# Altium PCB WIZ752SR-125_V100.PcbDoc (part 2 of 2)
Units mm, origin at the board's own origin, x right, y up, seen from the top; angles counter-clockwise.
Board outline 60 x 85 mm, 4 copper layers (Top Layer, Internal Plane 1, Internal Plane 2, Bottom Layer); 105 components, 107 nets, 391 pads, 152 vias.
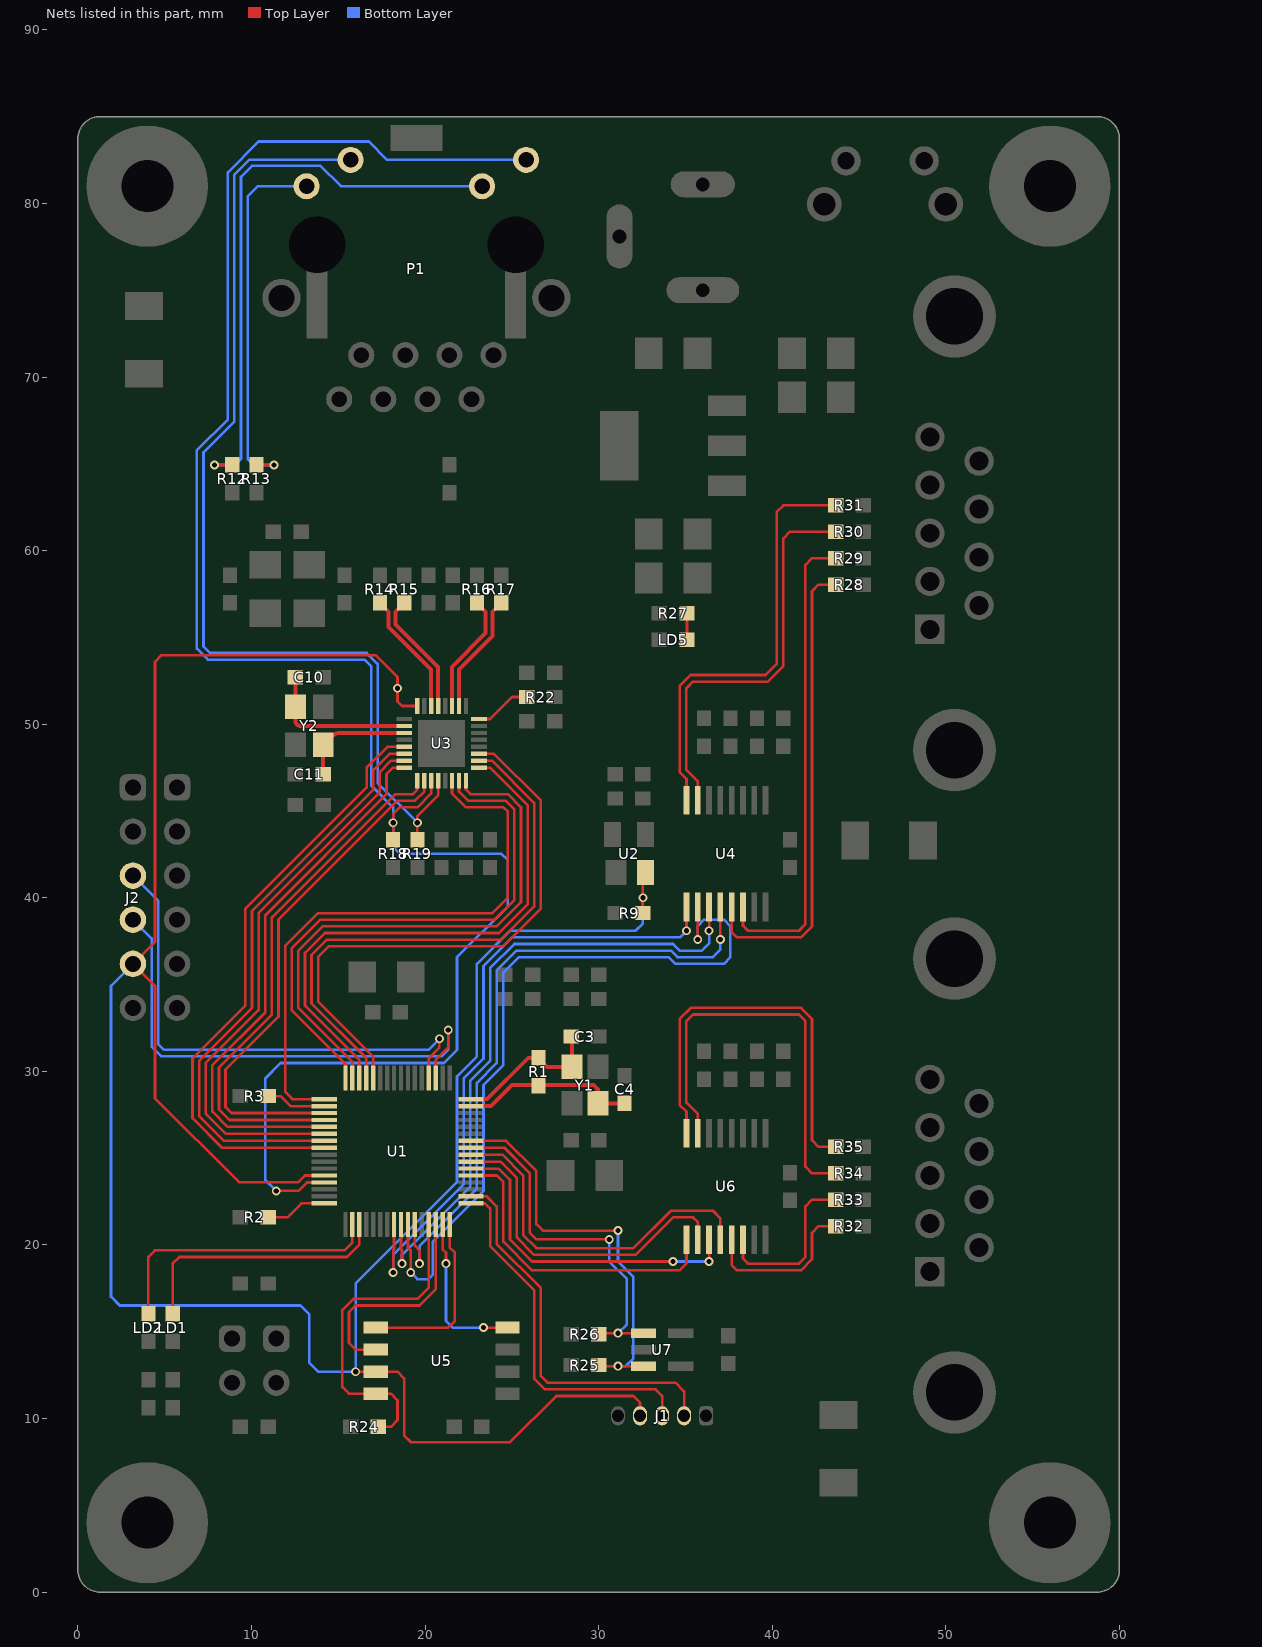
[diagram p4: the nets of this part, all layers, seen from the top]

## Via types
v1: diameter 0.762, hole 0.508, Top Layer to Bottom Layer, tented both sides, 87 vias
v2: diameter 0.508, hole 0.305, Top Layer to Bottom Layer, tented both sides, 65 vias

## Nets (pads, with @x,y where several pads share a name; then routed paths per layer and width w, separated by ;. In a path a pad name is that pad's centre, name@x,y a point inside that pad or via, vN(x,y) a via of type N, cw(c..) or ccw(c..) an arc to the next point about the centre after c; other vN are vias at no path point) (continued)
NetLD5_1: LD5.1 R27.1 | length 1.5
  Top Layer w0.152: LD5.1@35.09,54.864 R27.1@35.09,56.388
NetP1_L1: P1.L1 R13.2 | length 21.4
  Top Layer w0.152: R13.2@10.287,64.935 v2(11.303,64.935)
  Bottom Layer w0.152: v2(11.303,64.935) 10.122,64.935 9.779,65.278 9.779,80.391 10.378,80.99 P1.L1@13.175,80.99
NetP1_L3: P1.L3 R12.2 | length 33.6
  Top Layer w0.152: v2(7.874,64.935) R12.2@8.89,64.935
  Bottom Layer w0.152: v2(7.874,64.935) 9.055,64.935 9.398,65.278 9.398,81.534 10.033,82.169 13.97,82.169 15.149,80.99 P1.L3@23.285,80.99
NetR2_2: R2.2 U1.32 | length 3.6
  Top Layer w0.152: R2.2@10.96,21.59 12.065,21.59 12.875,22.4 U1.32@14.19,22.4
NetR3_2: R3.2 U1.18 | length 3.5
  Top Layer w0.152: R3.2@10.96,28.575 11.684,28.575 12.259,28 U1.18@14.19,28
NetR14_2: R14.2 U3.30 | length 7.2
  Top Layer w0.229: R14.2@17.399,56.985 17.907,56.477 17.907,55.595 20.355,53.147 U3.30@20.355,51.045
NetR15_2: R15.2 U3.29 | length 7.2
  Top Layer w0.229: R15.2@18.796,56.985 18.288,56.477 18.288,55.753 20.755,53.286 U3.29@20.755,51.045
NetR16_2: R16.2 U3.27 | length 7
  Top Layer w0.229: U3.27@21.555,51.045 21.555,53.305 23.495,55.245 23.495,56.477 R16.2@22.987,56.985
NetR17_2: R17.2 U3.26 | length 6.9
  Top Layer w0.229: U3.26@21.955,51.045 21.955,53.147 23.876,55.068 23.876,56.477 R17.2@24.384,56.985
NetR24_1: R24.1 U1.45 U5.4 | length 19.5
  Top Layer w0.152: R24.1@17.31,9.525 18.034,9.525 18.415,9.906 18.415,11.049 18.034,11.43 U5.4@17.155,11.43 15.621,11.43 15.24,11.811 15.24,16.256 15.875,16.891 19.558,16.891 20.215,17.548 U1.45@20.215,21.175
NetR25_1: R25.1 U1.58 U7.3 | length 23.8
  Top Layer w0.152: U1.58@22.64,26 24.673,26 26.416,24.257 26.416,21.209 26.797,20.828 v2(31.115,20.828) ; R25.1@30.01,13.081 30.071,13.02 v2(31.115,13.02) U7.3@32.58,13.02
  Bottom Layer w0.152: v2(31.115,13.02) 31.562,13.02 32.004,13.462 32.004,18.161 31.115,19.05 v2(31.115,20.828)
NetR26_1: R26.1 U1.57 U7.1 | length 20.8
  Top Layer w0.152: U1.57@22.64,25.6 24.565,25.6 26.035,24.13 26.035,20.701 26.416,20.32 v2(30.607,20.32) ; R26.1@30.01,14.859 30.071,14.92 v2(31.115,14.92) U7.1@32.58,14.92
  Bottom Layer w0.152: v2(30.607,20.32) 30.607,19.05 31.623,18.034 31.623,15.428 v2(31.115,14.92)
NetR28_1: R28.1 U4.13 | length 27.3
  Top Layer w0.152: U4.13@37.663,39.471 37.663,38.029 37.973,37.719 41.656,37.719 42.291,38.354 42.291,57.658 42.672,58.039 R28.1@43.65,58.039
NetR29_1: R29.1 U4.14 | length 27.6
  Top Layer w0.152: U4.14@38.313,39.471 38.313,38.395 38.608,38.1 41.529,38.1 41.91,38.481 41.91,59.182 42.291,59.563 R29.1@43.65,59.563
NetR30_1: R30.1 U4.7 | length 23.4
  Top Layer w0.152: U4.7@35.713,45.619 35.713,46.71 35.052,47.371 35.052,52.07 35.433,52.451 39.751,52.451 40.64,53.34 40.64,60.706 41.021,61.087 R30.1@43.65,61.087
NetR31_1: R31.1 U4.8 | length 25.2
  Top Layer w0.152: U4.8@35.063,45.619 35.063,46.852 34.671,47.244 34.671,52.197 35.306,52.832 39.624,52.832 40.259,53.467 40.259,62.23 40.64,62.611 R31.1@43.65,62.611
NetR32_1: R32.1 U6.13 | length 9.5
  Top Layer w0.152: U6.13@37.663,20.294 37.663,18.852 37.973,18.542 41.656,18.542 42.291,19.177 42.291,20.701 42.672,21.082 R32.1@43.65,21.082
NetR33_1: R33.1 U6.14 | length 9.8
  Top Layer w0.152: U6.14@38.313,20.294 38.313,19.218 38.608,18.923 41.529,18.923 41.91,19.304 41.91,22.225 42.291,22.606 R33.1@43.65,22.606
NetR34_1: R34.1 U6.7 | length 24.2
  Top Layer w0.152: U6.7@35.713,26.443 35.713,27.533 35.052,28.194 35.052,32.893 35.433,33.274 41.529,33.274 41.91,32.893 41.91,24.511 42.291,24.13 R34.1@43.65,24.13
NetR35_1: R35.1 U6.8 | length 23.4
  Top Layer w0.152: U6.8@35.063,26.443 35.063,27.675 34.671,28.067 34.671,33.02 35.306,33.655 41.656,33.655 42.291,33.02 42.291,26.035 42.672,25.654 R35.1@43.65,25.654
NetU1_40: U1.40 U4.9 | length 36.5
  Top Layer w0.152: v2(18.161,18.415) 18.161,19.685 18.215,19.739 U1.40@18.215,21.175 ; v2(35.063,38.1) U4.9@35.063,39.471
  Bottom Layer w0.152: v2(18.161,18.415) 18.161,19.431 22.225,23.495 22.225,29.591 23.368,30.734 23.368,36.068 25.019,37.719 34.682,37.719 v2(35.063,38.1)
NetU1_41: U1.41 U4.11 | length 37
  Top Layer w0.152: U1.41@18.615,21.175 18.615,19.739 18.669,19.685 v2(18.669,18.923) ; v2(36.363,38.1) U4.11@36.363,39.471
  Bottom Layer w0.152: v2(18.669,18.923) 18.669,19.431 22.606,23.368 22.606,29.464 23.749,30.607 23.749,35.941 25.146,37.338 34.29,37.338 34.671,36.957 35.941,36.957 36.363,37.379 v2(36.363,38.1)
NetU1_42: U1.42 U4.10 | length 43.8
  Top Layer w0.152: U1.42@19.015,21.175 19.015,19.847 19.177,19.685 v2(19.177,18.415) ; v2(35.713,37.592) U4.10@35.713,39.471
  Bottom Layer w0.152: v2(19.177,18.415) 19.558,18.034 20.193,18.034 20.447,18.288 20.447,20.193 23.368,23.114 23.368,29.21 24.511,30.353 24.511,35.687 25.4,36.576 34.036,36.576 34.417,36.195 37.211,36.195 37.592,36.576 37.592,38.354 37.211,38.735 36.068,38.735 35.713,38.38 v2(35.713,37.592)
NetU1_43: U1.43 U4.12 | length 37.2
  Top Layer w0.152: U1.43@19.415,21.175 19.415,19.955 19.685,19.685 v2(19.685,18.923) ; v2(37.013,37.592) U4.12@37.013,39.471
  Bottom Layer w0.152: v2(19.685,18.923) 19.685,19.939 22.987,23.241 22.987,29.337 24.13,30.48 24.13,35.814 25.273,36.957 34.163,36.957 34.544,36.576 36.576,36.576 37.013,37.013 v2(37.013,37.592)
NetU1_46: U1.46 U5.2 | length 12.7
  Top Layer w0.152: U5.2@17.155,13.97 16.002,13.97 15.621,14.351 15.621,16.129 16.002,16.51 19.685,16.51 20.615,17.44 U1.46@20.615,21.175
NetU1_47: U1.47 U5.8 | length 9.3
  Top Layer w0.152: U1.47@21.015,21.175 21.015,19.752 21.209,19.558 v2(21.209,18.923) ; v2(23.368,15.24) U5.8@24.755,15.24
  Bottom Layer w0.152: v2(21.209,18.923) 21.209,15.621 21.59,15.24 v2(23.368,15.24)
NetU1_48: U1.48 U5.1 | length 10.4
  Top Layer w0.152: U5.1@17.155,15.24 21.336,15.24 21.717,15.621 21.717,19.558 21.415,19.86 U1.48@21.415,21.175
NetU1_53: U1.53 U6.9 | length 18.2
  Top Layer w0.152: U1.53@22.64,24 24.133,24 24.511,23.622 24.511,20.193 26.162,18.542 34.671,18.542 35.063,18.934 U6.9@35.063,20.294
NetU1_54: U1.54 U6.11 | length 19.2
  Top Layer w0.152: U1.54@22.64,24.4 24.241,24.4 24.892,23.749 24.892,20.32 26.162,19.05 v2(34.29,19.05) ; v2(36.363,19.05) U6.11@36.363,20.294
  Bottom Layer w0.152: v2(34.29,19.05) v2(36.363,19.05)
NetU1_55: U1.55 U6.10 | length 19.3
  Top Layer w0.152: U1.55@22.64,24.8 24.349,24.8 25.273,23.876 25.273,20.447 26.289,19.431 32.131,19.431 34.29,21.59 35.433,21.59 35.713,21.31 U6.10@35.713,20.294
NetU1_56: U1.56 U6.12 | length 20.9
  Top Layer w0.152: U1.56@22.64,25.2 24.457,25.2 25.654,24.003 25.654,20.574 26.416,19.812 32.004,19.812 34.163,21.971 36.576,21.971 37.013,21.534 U6.12@37.013,20.294
PHY_AD0: P1.L4 R18.1 U1.29 U3.11 | length 113.3
  Top Layer w0.152: v2(11.43,23.114) 12.7,23.114 13.186,23.6 U1.29@14.19,23.6 ; R18.1@18.161,43.345 v2(18.161,44.323) 18.161,44.831 18.542,45.212 19.558,45.212 20.355,46.009 U3.11@20.355,46.745
  Bottom Layer w0.152: v2(11.43,23.114) 10.795,23.749 10.795,29.591 11.684,30.48 21.082,30.48 21.844,31.242 21.844,36.576 24.765,39.497 24.765,42.164 24.384,42.545 18.542,42.545 18.161,42.926 v2(18.161,44.323) 18.161,45.212 16.891,46.482 16.891,53.34 16.51,53.721 7.493,53.721 6.858,54.356 6.858,65.786 8.636,67.564 8.636,81.788 10.414,83.566 16.764,83.566 17.82,82.51 P1.L4@25.825,82.51
PHY_AD3: P1.L2 R19.1 U3.12 | length 59.4
  Top Layer w0.152: R19.1@19.558,43.345 v2(19.558,44.323) 19.558,44.704 20.755,45.901 U3.12@20.755,46.745
  Bottom Layer w0.152: P1.L2@15.715,82.51 9.866,82.51 9.017,81.661 9.017,67.437 7.239,65.659 7.239,54.483 7.62,54.102 16.637,54.102 17.272,53.467 17.272,46.609 v2(19.558,44.323)
RSTN: J1.4 J2.5 R9.1 U1.28 U2.2 U3.32 U5.3 | length 155.4
  Top Layer w0.152: U1.28@14.19,24 13.078,24 12.7,23.622 9.271,23.622 4.445,28.448 4.445,34.925 J2.5@3.175,36.195 4.445,37.465 4.445,53.594 4.826,53.975 17.145,53.975 18.415,52.705 v2(18.415,52.07) 18.415,51.308 18.678,51.045 U3.32@19.555,51.045 ; v2(16.002,12.7) U5.3@17.155,12.7 18.415,12.7 18.796,12.319 18.796,9.017 19.177,8.636 24.892,8.636 27.559,11.303 32.004,11.303 32.385,10.922 J1.4@32.385,10.16 ; R9.1@32.55,39.116 v2(32.55,40.005) 32.55,41.295 U2.2@32.7,41.445
  Bottom Layer w0.152: J2.5@3.175,36.195 1.905,34.925 1.905,17.018 2.413,16.51 12.827,16.51 13.335,16.002 13.335,13.208 13.843,12.7 v2(16.002,12.7) 16.002,17.78 21.844,23.622 21.844,29.718 22.987,30.861 22.987,36.195 24.892,38.1 32.131,38.1 32.55,38.519 v2(32.55,40.005)
RXC: U1.17 U3.14 | length 34.1
  Top Layer w0.152: U1.17@14.19,28.4 12.367,28.4 11.938,28.829 11.938,37.211 13.843,39.116 23.876,39.116 24.765,40.005 24.765,44.958 24.511,45.212 22.352,45.212 21.555,46.009 U3.14@21.555,46.745
RXD0: U1.13 U3.18 | length 32.5
  Top Layer w0.152: U1.13@16.615,29.625 16.615,30.756 13.462,33.909 13.462,36.703 14.351,37.592 24.384,37.592 26.289,39.497 26.289,45.466 23.86,47.895 U3.18@23.105,47.895
RXD1: U1.14 U3.17 | length 31.9
  Top Layer w0.152: U1.14@16.215,29.625 16.215,30.648 13.081,33.782 13.081,36.83 14.224,37.973 24.257,37.973 25.908,39.624 25.908,45.339 23.752,47.495 U3.17@23.105,47.495
RXD2: U1.15 U3.16 | length 32.2
  Top Layer w0.152: U1.15@15.815,29.625 15.815,30.54 12.7,33.655 12.7,36.957 14.097,38.354 24.13,38.354 25.527,39.751 25.527,45.212 24.765,45.974 22.606,45.974 22.355,46.225 U3.16@22.355,46.745
RXD3: U1.16 U3.15 | length 32.2
  Top Layer w0.152: U1.16@15.415,29.625 15.415,30.432 12.319,33.528 12.319,37.084 13.97,38.735 24.003,38.735 25.146,39.878 25.146,45.085 24.638,45.593 22.479,45.593 21.955,46.117 U3.15@21.955,46.745
RXDV: U1.12 U3.19 | length 33.2
  Top Layer w0.152: U1.12@17.015,29.625 17.015,30.864 13.843,34.036 13.843,36.576 14.478,37.211 24.511,37.211 26.67,39.37 26.67,45.593 23.968,48.295 U3.19@23.105,48.295
STATUS_1: LD1.2 U1.35 | length 15.2
  Top Layer w0.152: LD1.2@5.461,16.04 5.461,18.923 5.842,19.304 15.494,19.304 16.215,20.025 U1.35@16.215,21.175
STATUS_2: LD2.2 U1.34 | length 16.4
  Top Layer w0.152: LD2.2@4.064,16.04 4.064,19.304 4.445,19.685 15.367,19.685 15.815,20.133 U1.34@15.815,21.175
SWCLK: J1.3 U1.49 | length 21
  Top Layer w0.152: U1.49@22.64,22.4 23.447,22.4 23.749,22.098 23.749,19.939 26.289,17.399 26.289,12.319 26.924,11.684 33.274,11.684 33.655,11.303 J1.3@33.655,10.16
SWDIO: J1.2 U1.50 | length 22.6
  Top Layer w0.152: U1.50@22.64,22.8 23.555,22.8 24.13,22.225 24.13,20.066 26.67,17.526 26.67,12.446 27.051,12.065 34.417,12.065 34.925,11.557 J1.2@34.925,10.16
TEST: R22.1 U3.24 | length 3.3
  Top Layer w0.152: U3.24@23.105,50.295 23.752,50.295 25.019,51.562 R22.1@25.87,51.562
TXC: U1.19 U3.10 | length 30
  Top Layer w0.152: U1.19@14.19,27.6 8.849,27.6 8.509,27.94 8.509,30.099 11.557,33.147 11.557,38.735 18.415,45.593 19.431,45.593 19.955,46.117 U3.10@19.955,46.745
TXD00: U1.20 U3.9 | length 30.6
  Top Layer w0.152: U1.20@14.19,27.2 8.741,27.2 8.128,27.813 8.128,30.226 11.176,33.274 11.176,38.862 18.288,45.974 19.304,45.974 19.555,46.225 U3.9@19.555,46.745
TXD1: U1.21 U3.8 | length 31.6
  Top Layer w0.152: U1.21@14.19,26.8 8.633,26.8 7.747,27.686 7.747,30.353 10.795,33.401 10.795,38.989 17.78,45.974 17.78,47.117 18.158,47.495 U3.8@18.805,47.495
TXD2: U1.22 U3.7 | length 32.8
  Top Layer w0.152: U1.22@14.19,26.4 8.525,26.4 7.366,27.559 7.366,30.48 10.414,33.528 10.414,39.116 17.399,46.101 17.399,47.244 18.05,47.895 U3.7@18.805,47.895
TXD3: U1.23 U3.6 | length 34.1
  Top Layer w0.152: U1.23@14.19,26 8.417,26 6.985,27.432 6.985,30.607 10.033,33.655 10.033,39.243 17.018,46.228 17.018,47.371 17.942,48.295 U3.6@18.805,48.295
TXEN: U1.24 U3.5 | length 35.3
  Top Layer w0.152: U1.24@14.19,25.6 8.309,25.6 6.604,27.305 6.604,30.734 9.652,33.782 9.652,39.37 16.637,46.355 16.637,47.498 17.834,48.695 U3.5@18.805,48.695
U_RXD2: J2.3 U1.4 | length 29.4
  Top Layer w0.152: U1.4@20.215,29.625 20.215,30.756 20.828,31.369 v2(20.828,31.877)
  Bottom Layer w0.152: J2.3@3.175,41.275 4.635,39.814 4.635,31.559 4.953,31.242 20.193,31.242 v2(20.828,31.877)
U_TXD2: J2.4 U1.3 | length 29.4
  Top Layer w0.152: U1.3@20.615,29.625 20.615,30.648 21.336,31.369 v2(21.336,32.385)
  Bottom Layer w0.152: J2.4@3.175,38.735 4.255,37.655 4.255,31.432 4.826,30.861 20.955,30.861 21.336,31.242 v2(21.336,32.385)
XIN: C4.2 R1.1 U1.63 Y1.3 | length 10.3
  Top Layer w0.229: U1.63@22.64,28 23.809,28 25.019,29.21 29.718,29.21 29.96,28.968 Y1.3@29.96,28.16 31.492,28.16 C4.2@31.496,28.156
XOUT: C3.2 R1.2 U1.64 Y1.1 | length 8.8
  Top Layer w0.229: U1.64@22.64,28.4 23.574,28.4 25.946,30.772 R1.2@26.543,30.772 26.543,30.734 27.017,30.26 Y1.1@28.46,30.26 28.46,31.954 C3.2@28.41,32.004
XTAL1: C10.2 U3.2 Y2.1 | length 8.9
  Top Layer w0.229: C10.2@12.535,52.705 Y2.1@12.535,51.011 12.535,50.203 ccw(c12.843,50.203) 12.843,49.895 U3.2@18.805,49.895
XTAL2: C11.2 U3.3 Y2.3 | length 6.6
  Top Layer w0.229: C11.2@14.135,47.117 Y2.3@14.135,48.811 14.605,49.281 cw(c15.122,48.764) 15.122,49.495 U3.3@18.805,49.495
pads on no net: J6.1 J6.4 J6.6 J6.9 J7.1 J7.4 J7.6 J7.9 P1. P1.R4 P1.R5 P1.R6 U1.30 U1.31 U1.33 U1.37 U1.38 U1.44 U1.51 U1.52 U1.59 U1.60 U3.1 U3.21

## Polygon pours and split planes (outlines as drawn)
CH_GND on Top Layer "Top Layer-net" (solid, remove dead copper, pour order 18): 0.762,7.366 0.508,7.112 0.508,1.016 1.016,0.508 1.651,0.508 59.055,0.508 59.563,1.016 59.563,1.778 59.563,83.947 59.055,84.455 58.801,84.455 51.943,84.455 51.689,84.201 51.689,83.947 51.689,81.534 51.308,81.153 50.927,81.153 42.037,81.153 41.783,80.899 41.783,80.518 41.783,78.613 42.037,78.359 42.926,78.359 47.117,78.359 47.498,77.978 47.498,77.597 47.498,69.723 47.752,69.469 48.514,69.469 54.356,69.469 54.737,69.088 54.737,68.58 54.737,52.832 54.356,52.451 53.975,52.451 47.879,52.451 47.498,52.07 47.498,49.403 47.498,32.893 47.879,32.512 54.356,32.512 54.737,32.131 54.737,31.496 54.737,15.875 54.356,15.494 53.594,15.494 47.879,15.494 47.498,15.113 47.498,14.859 47.498,7.747 47.117,7.366 46.736,7.366
GND on Top Layer "Top Layer-net" (solid, remove dead copper, pour order 14): 29.464,69.977 29.21,70.231 29.21,70.358 29.21,72.771 30.226,73.787 30.226,81.026 31.242,82.042 32.258,82.042 37.719,82.042 37.973,81.788 37.973,81.534 37.973,80.391 37.719,80.137 37.338,80.137 33.401,80.137 33.02,79.756 33.02,79.375 33.02,74.168 33.782,73.406 34.036,73.152 34.036,71.247 34.036,70.231 33.782,69.977
IP_3.3V on Top Layer "Top Layer-net" (solid, remove dead copper, pour order 10): 20.574,44.831 20.447,44.704 20.447,42.926 20.574,42.799 22.86,42.799 22.86,44.704 22.733,44.831
3.3V on Top Layer "Top Layer-net" (solid, remove dead copper, pour order 6): 21.844,42.291 21.844,40.386 21.971,40.259 24.13,40.259 24.257,40.386 24.257,42.164 24.13,42.291
3.3V on Top Layer "Top Layer-net" (solid, remove dead copper, pour order 4): 34.036,56.007 33.782,55.753 33.274,55.753 29.464,55.753 29.21,56.007 29.21,56.642 29.21,69.215 29.464,69.469 29.845,69.469 33.782,69.469 34.036,69.215 34.036,68.834 34.036,67.183 34.417,66.802 34.798,66.802 38.608,66.802 38.735,66.675 38.735,66.421 38.735,65.405 38.608,65.278 38.1,65.278 34.417,65.278 34.036,64.897
5V on Top Layer "Top Layer-net" (solid, remove dead copper, pour order 2): 34.544,69.977 34.544,67.818 34.798,67.564 35.433,67.564 39.751,67.564 42.037,67.564 42.291,67.818 42.291,68.199 42.291,75.819 42.037,76.073 41.783,76.073 33.782,76.073 33.528,75.819 33.528,74.803 33.528,74.422 34.544,73.406
CH_GND on Top Layer "Top Layer-net" (solid, remove dead copper, pour order 0): 0.762,73.152 0.508,73.406 0.508,83.947 1.016,84.455 10.541,84.455 10.795,84.201 10.795,83.82 10.795,77.597 12.573,75.819 12.827,75.565 12.827,74.168 12.827,73.406 12.573,73.152
GND on Top Layer "Top Layer-gnd" (solid, remove dead copper, pour order 28): 0.762,70.993 0.508,70.739 0.508,9.144 0.762,8.89 41.275,8.89 41.783,9.398 45.72,9.398 45.974,9.652 45.974,41.021 45.593,41.402 45.593,45.212 45.974,45.593 45.974,75.819 45.72,76.073 45.466,76.073 42.933,76.073 42.679,75.819 42.679,67.571 42.291,67.183 41.656,67.183 39.37,67.183 39.116,66.929 39.116,65.151 38.862,64.897 38.1,64.897 34.585,64.897 34.424,64.736 34.424,55.633 34.163,55.372 29.21,55.372 28.829,55.753 28.829,65.659 28.575,65.913 6.604,65.913 6.223,66.294 6.223,70.739 5.969,70.993
5V on Bottom Layer "Top Layer-net" (solid, remove dead copper, pour order 22): 33.782,76.073 33.528,75.819 33.528,74.422 34.544,73.406 34.544,71.247 34.544,70.104 34.798,69.85 39.116,69.85 39.37,70.104 39.37,75.819 39.116,76.073
CH_GND on Bottom Layer "Top Layer-net" (solid, remove dead copper, pour order 20): 1.016,84.455 0.508,83.947 0.508,73.406 0.762,73.152 7.493,73.152 7.747,73.406 7.747,84.201 7.493,84.455
CH_GND on Bottom Layer "Top Layer-net" (solid, remove dead copper, pour order 16): 0.762,7.366 0.508,7.112 0.508,1.016 1.016,0.508 1.651,0.508 59.055,0.508 59.563,1.016 59.563,1.778 59.563,83.947 59.055,84.455 58.801,84.455 51.943,84.455 51.689,84.201 51.689,83.947 51.689,81.534 51.308,81.153 50.927,81.153 42.037,81.153 41.783,80.899 41.783,80.518 41.783,78.613 42.037,78.359 42.926,78.359 47.117,78.359 47.498,77.978 47.498,77.597 47.498,69.723 47.752,69.469 48.514,69.469 54.356,69.469 54.737,69.088 54.737,68.58 54.737,52.832 54.356,52.451 53.975,52.451 47.879,52.451 47.498,52.07 47.498,49.403 47.498,32.893 47.879,32.512 54.356,32.512 54.737,32.131 54.737,31.496 54.737,15.875 54.356,15.494 53.594,15.494 47.879,15.494 47.498,15.113 47.498,14.859 47.498,7.747 47.117,7.366 46.736,7.366
IP_3.3V on Bottom Layer "Top Layer-net" (solid, remove dead copper, pour order 12): 20.574,44.831 20.447,44.704 20.447,43.942 20.574,43.815 22.733,43.815 22.86,43.942 22.86,44.704 22.733,44.831
3.3V on Bottom Layer "Top Layer-net" (solid, remove dead copper, pour order 8): 21.971,41.275 21.844,41.148 21.844,40.386 21.971,40.259 24.13,40.259 24.257,40.386 24.257,41.148 24.13,41.275
3.3V on Bottom Layer "Top Layer-gnd" (solid, remove dead copper, pour order 24): 29.464,62.23 29.21,61.976 29.21,61.849 29.21,59.944 29.464,59.69 31.496,59.69 31.75,59.944 31.75,61.976 31.496,62.23
GND on Bottom Layer "Top Layer-gnd" (solid, remove dead copper, pour order 30): 0.762,70.993 0.508,70.739 0.508,70.612 0.508,9.144 0.762,8.89 45.72,8.89 45.974,9.144 45.974,10.287 45.974,75.819 45.72,76.073 45.212,76.073 40.005,76.073 34.036,76.073 33.782,75.819 33.782,75.184 33.782,73.914 33.401,73.533 32.893,73.533 29.972,73.533 29.21,72.771 29.083,72.644 29.083,71.628 29.083,66.294 28.702,65.913 28.448,65.913 6.604,65.913 6.223,66.294 6.223,70.739 5.969,70.993
GND on Internal Plane 1 (split plane): 45.972,68.707 45.981,68.587 46.009,68.471 46.055,68.36 46.118,68.258 46.196,68.167 46.287,68.089 46.389,68.026 46.5,67.98 46.616,67.952 46.736,67.943 53.211,67.943 53.211,53.977 46.736,53.977 46.616,53.968 46.5,53.94 46.389,53.894 46.287,53.831 46.196,53.753 46.118,53.662 46.055,53.56 46.009,53.449 45.981,53.333 45.972,53.213 45.972,31.75 45.981,31.63 46.009,31.514 46.055,31.403 46.118,31.301 46.196,31.21 46.287,31.132 46.389,31.069 46.5,31.023 46.616,30.995 46.736,30.986 53.211,30.986 53.211,17.02 46.736,17.02 46.616,17.011 46.5,16.983 46.389,16.937 46.287,16.874 46.196,16.796 46.118,16.705 46.055,16.603 46.009,16.492 45.981,16.376 45.972,16.256 45.972,8.892 0.51,8.892 0.51,71.372 6.221,71.372 6.221,66.675 6.23,66.555 6.258,66.439 6.304,66.328 6.367,66.226 6.445,66.135 6.536,66.057 6.638,65.994 6.749,65.948 6.865,65.92 6.985,65.911 28.321,65.911 28.441,65.92 28.557,65.948 28.668,65.994 28.77,66.057 28.861,66.135 28.939,66.226 29.002,66.328 29.048,66.439 29.076,66.555 29.085,66.675 29.085,72.708 29.908,73.531 33.02,73.531 33.14,73.54 33.256,73.568 33.367,73.614 33.469,73.677 33.56,73.755 33.638,73.846 33.701,73.948 33.747,74.059 33.775,74.175 33.784,74.295 33.784,76.706 45.972,76.706
CH_GND on Internal Plane 1 (split plane): 154 vertices, not listed, extent 0.509,0.509 59.491,84.491
IP_3.3V on Internal Plane 2 (split plane): 6.221,66.675 6.23,66.555 6.258,66.439 6.304,66.328 6.367,66.226 6.445,66.135 6.536,66.057 6.638,65.994 6.749,65.948 6.865,65.92 6.985,65.911 26.414,65.911 26.414,53.975 26.423,53.909 26.448,53.847 26.489,53.794 26.542,53.753 26.604,53.728 26.67,53.719 28.954,53.719 28.954,42.801 20.32,42.801 20.254,42.792 20.192,42.767 20.139,42.726 20.098,42.673 20.073,42.611 20.064,42.545 20.064,39.626 9.146,39.626 9.146,48.895 9.137,48.961 9.112,49.023 9.071,49.076 9.018,49.117 8.956,49.142 8.89,49.151 0.51,49.151 0.51,71.372 6.221,71.372
3.3V on Internal Plane 2 (split plane): 45.972,68.707 45.974,68.677 45.974,53.243 45.972,53.213 45.972,31.75 45.974,31.72 45.974,16.286 45.972,16.256 45.972,8.892 0.51,8.892 0.51,48.639 8.634,48.639 8.634,39.37 8.643,39.304 8.668,39.242 8.709,39.189 8.762,39.148 8.824,39.123 8.89,39.114 20.32,39.114 20.386,39.123 20.448,39.148 20.501,39.189 20.542,39.242 20.567,39.304 20.576,39.37 20.576,42.289 29.21,42.289 29.276,42.298 29.338,42.323 29.391,42.364 29.432,42.417 29.457,42.479 29.466,42.545 29.466,53.975 29.457,54.041 29.432,54.103 29.391,54.156 29.338,54.197 29.276,54.222 29.21,54.231 26.926,54.231 26.926,65.911 28.321,65.911 28.441,65.92 28.557,65.948 28.668,65.994 28.77,66.057 28.861,66.135 28.939,66.226 29.002,66.328 29.048,66.439 29.076,66.555 29.085,66.675 29.085,72.708 29.908,73.531 33.02,73.531 33.14,73.54 33.256,73.568 33.367,73.614 33.469,73.677 33.56,73.755 33.638,73.846 33.701,73.948 33.747,74.059 33.775,74.175 33.784,74.295 33.784,76.706 45.972,76.706

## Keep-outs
Keep-Out Layer:
  the board outline again, w0.127
  text ".Layer_Name" at 9.398,92.71 h1.52

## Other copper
Top Layer:
  pour cut-out: 27.432,28.448 27.686,28.194 27.686,27.432 27.813,27.305 32.004,27.305 32.131,27.432 32.131,30.988 32.004,31.115 31.115,31.115 30.861,31.369 30.861,32.639 30.734,32.766 25.908,32.766 25.781,32.639 25.781,28.575 25.908,28.448
  pour cut-out: 11.938,53.467 11.684,53.213 11.684,46.609 11.938,46.355 14.732,46.355 14.986,46.609 14.986,53.213 14.732,53.467
  text ".Layer_Name" at 9.398,92.71 h1.52
Bottom Layer:
  pour cut-out: 27.813,31.115 27.686,30.988 27.686,27.432 27.813,27.305 30.607,27.305 30.734,27.432 30.734,30.988 30.607,31.115
  pour cut-out: 11.938,51.816 11.811,51.689 11.811,48.133 11.938,48.006 14.732,48.006 14.859,48.133 14.859,51.689 14.732,51.816
  text ".Layer_Name" at 9.398,92.71 h1.52
Internal Plane 1 (plane layer: these items are gaps in the copper):
  rectangle: 6.985,66.675 28.321,72.898
  rectangle: 27.686,27.305 30.734,31.115
  rectangle: 11.811,48.006 14.859,51.816
  lines w1.524: 0.254,8.128 46.736,8.128 46.736,16.256 53.975,16.256 53.975,31.75 46.736,31.75 46.736,53.213 53.975,53.213 53.975,68.707 46.736,68.707 46.736,77.47 33.02,77.47 33.02,74.295 29.591,74.295 28.321,73.025 28.321,66.675 6.985,66.675 6.985,72.136 0.381,72.136
  text "GND" at 9.398,92.742 h1.52
Internal Plane 2 (plane layer: these items are gaps in the copper):
  rectangle: 33.02,77.47 45.974,85
  rectangle: 28.575,73.531 33.02,85
  rectangle: 6.985,66.675 28.575,85
  rectangle: 0,71.374 7.747,85
  rectangle: 45.974,7.493 60,85
  rectangle: 0,0 60,8.128
  rectangle: 27.686,27.305 30.734,31.115
  rectangle: 11.811,48.006 14.859,51.816
  lines w0.508: 0,48.895 8.89,48.895 8.89,39.37 20.32,39.37 20.32,42.545 29.21,42.545 29.21,53.975 26.67,53.975 26.67,66.675 28.321,66.675
  lines w1.524: 0.254,8.128 46.736,8.128 46.736,16.256 53.975,16.256 53.975,31.75 46.736,31.75 46.736,53.213 53.975,53.213 53.975,68.707 46.736,68.707 46.736,77.47 33.02,77.47 33.02,74.295 29.591,74.295 28.321,73.025 28.321,66.675 6.985,66.675 6.985,72.136 0.254,72.136
  text "POWER" at 9.398,92.742 h1.52
  text "3.3V" at 32.131,60.579 h0.76
  text "IP_3.3V" at 9.398,40.132 h0.76

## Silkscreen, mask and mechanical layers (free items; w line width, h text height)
Top Overlay:
  region: 34.255,0.762 34.255,7.762 8.255,7.762 8.255,0.762
  text ".Layer_Name" at 9.398,92.742 h1.52
  text "5V" at 40.64,74.168 h0.76
  text "POWER" at 38.227,54.483 h0.76
  text "ISP" at 2.54,49.022 h0.76
  text "GPIO" at 4.699,49.022 h0.76
  text "RS-232C-1" at 52.07,44.323 h0.76
  text "RS-232C-2" at 52.07,39.878 h0.76
  text "LED-2" at 23.876,36.449 h0.76
  text "LED-1" at 23.876,32.512 h0.76
  text "STATUS-2" at 4.445,19.431 h0.76 r90
  text "STATUS-1" at 5.842,19.431 h0.76 r90
  text "APP BOOT" at 7.239,12.446 h0.76 r90
  text "BOOT" at 13.843,12.446 h0.76 r90
  text "SWD" at 37.211,9.271 h0.76
  text "WIZ752SR-125 V1.0" at 35.433,1.27 h1.52
Bottom Overlay:
  text ".Layer_Name" at 9.398,92.71 h1.52
Top Paste:
  text ".Layer_Name" at 9.398,92.71 h1.52
Bottom Paste:
  text ".Layer_Name" at 9.398,92.71 h1.52
Top Solder:
  text ".Layer_Name" at 9.398,92.71 h1.52
Bottom Solder:
  text ".Layer_Name" at 9.398,92.71 h1.52
Drill Guide:
  text ".Layer_Name" at 9.398,92.71 h1.52
Mechanical 2:
  lines w0.127: 71.196,16.129 97.358,16.129 ; 71.196,18.923 97.358,18.923 ; 0,1.27 ccw(c1.27,1.27) 1.27,0 58.73,0 ccw(c58.73,1.27) 60,1.27 60,83.73 ccw(c58.73,83.73) 58.73,85 1.27,85 ccw(c1.27,83.73) 0,83.73 0,1.27 ; 69.85,4.775 ccw(c70.561,4.775) 70.561,4.064 97.739,4.064 ccw(c97.739,4.775) 98.45,4.775 98.45,24.003 ccw(c97.739,24.003) 97.739,24.714 70.561,24.714 ccw(c70.561,24.003) 69.85,24.003 69.85,4.775
  text "BOARD NAME : WIZ752SR-125" at 0,103.886 h1.52
  text "VERSION : V100" at 0,101.092 h1.52
  text "SIZE : 60mX85mX1.6T" at 0,98.298 h1.52
  text "GERBER DATE : 2017.12.18" at 0,95.504 h1.52
  text "LAYER :" at 0,92.71 h1.52
  text "Layer Stack Up Detail for:" at 71.323,22.606 h1.02
  text "WIZ752SR-125_V100.PcbDoc" at 71.196,20.193 h1.27
  text "Layer Name : 4L  1.6T" at 71.323,17.018 h1.02
  text "Top Layer" at 71.196,13.335 h1.52
  text "GND" at 71.196,10.541 h1.52
  text "POWER" at 71.196,7.874 h1.52
  text "Bottom Layer" at 71.196,5.334 h1.52
  text "KS Technology artwork" at 69.85,0 h5.08
Drill Drawing:
  text ".Layer_Name" at 9.398,92.71 h1.52
  text ".Legend" at 71.882,27.432 h1.02

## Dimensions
0,1.27 to 60,1.27 on Mechanical 2
1.27,0 to 1.27,85 on Mechanical 2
